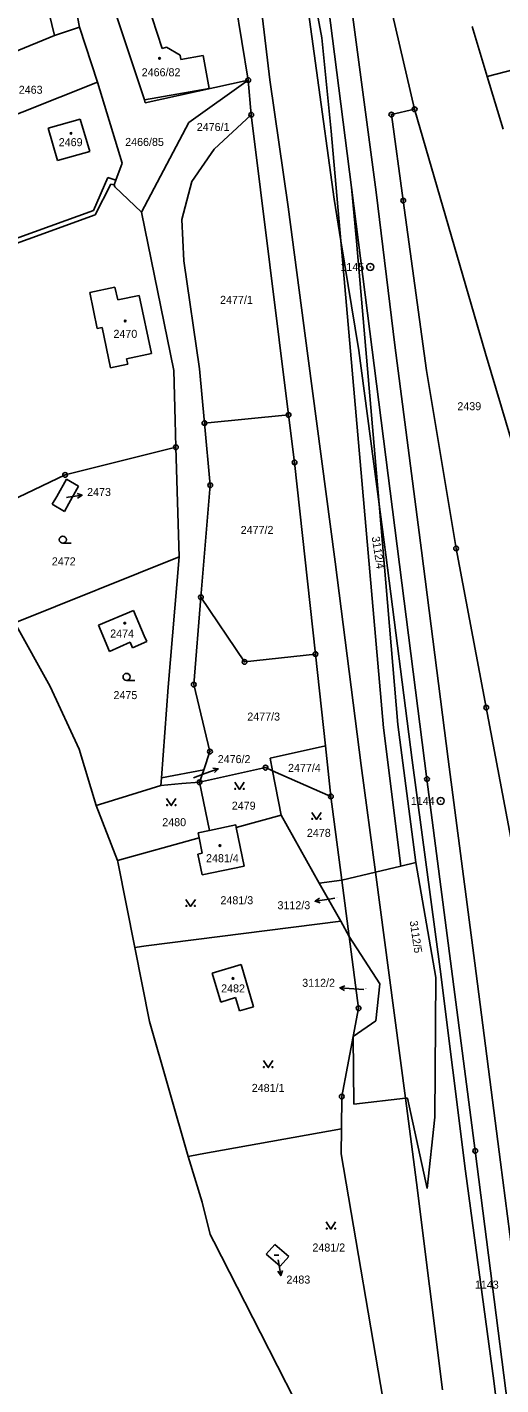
# Model space of a CAD drawing. Extents: x -736345 to -729997, y -1130177 to -1122501.
# Drawn here: x -733345 to -733244.4, y -1127962.5 to -1127674.1 of the extents above; entities that cross this region are included whole.
import ezdxf

# ---------------------------------------------------------------- set-up
doc = ezdxf.new("R2010")
doc.units = 0
for name, color, linetype in [('Vrstva 1', 7, 'Continuous'), ('Vrstva 10', 7, 'Continuous'), ('Vrstva 16', 7, 'Continuous'), ('Vrstva 17', 7, 'Continuous'), ('Vrstva 18', 7, 'Continuous'), ('Vrstva 19', 7, 'Continuous'), ('Vrstva 25', 7, 'Continuous'), ('Vrstva 4', 7, 'Continuous')]:
    doc.layers.add(name, color=color, linetype=linetype)

msp = doc.modelspace()

# ---------------------------------------------------------------- linework, layer by layer
at = {"layer": 'Vrstva 1'}
for points in [[(-733333.91, -1127674.1), (-733339.71, -1127643.99)], [(-733288.73, -1127642.56), (-733282.45, -1127676.33)], [(-733303.42, -1127652.45), (-733298.06, -1127685.32)], [(-733282.85, -1127655.34), (-733276.12, -1127708.15)], [(-733262.71, -1127691.52), (-733271.41, -1127654.27)], [(-733341.96, -1127664.36), (-733339.19, -1127675.85)], [(-733319.54, -1127668.85), (-733316.3, -1127678.59)], [(-733320.11, -1127689.5), (-733326.23, -1127671.02)], [(-733409.51, -1127704.75), (-733339.19, -1127675.85)], [(-733339.19, -1127675.85), (-733333.91, -1127674.1)], [(-733333.91, -1127674.1), (-733330.07, -1127685.76)], [(-733282.45, -1127676.33), (-733280.41, -1127696.21)], [(-733250.49, -1127673.94), (-733247.3, -1127684.57)], [(-733316.3, -1127678.59), (-733315.39, -1127678.31)], [(-733315.39, -1127678.31), (-733312.5, -1127680.04)], [(-733247.3, -1127684.57), (-733217.33, -1127676.81)], [(-733312.5, -1127680.04), (-733312.34, -1127680.96)], [(-733312.34, -1127680.96), (-733307.65, -1127680.12)], [(-733307.65, -1127680.12), (-733306.36, -1127687.1)], [(-733243.94, -1127695.79), (-733247.3, -1127684.57)], [(-733402.84, -1127714.76), (-733330.07, -1127685.76)], [(-733330.07, -1127685.76), (-733324.85, -1127703.01)], [(-733306.36, -1127687.1), (-733320.11, -1127689.5)], [(-733298.06, -1127685.32), (-733319.96, -1127690.18)], [(-733298.06, -1127685.32), (-733310.68, -1127694.33)], [(-733297.41, -1127692.7), (-733298.06, -1127685.32)], [(-733319.96, -1127690.18), (-733320.11, -1127689.5)], [(-733333.74, -1127693.66), (-733340.55, -1127695.53)], [(-733331.71, -1127700.53), (-733333.74, -1127693.66)], [(-733297.41, -1127692.7), (-733305.27, -1127699.97)], [(-733297.41, -1127692.7), (-733289.47, -1127756.46)], [(-733267.66, -1127692.67), (-733262.71, -1127691.52)], [(-733265.12, -1127710.93), (-733267.66, -1127692.67)], [(-733262.71, -1127691.52), (-733247.65, -1127743.42)], [(-733340.55, -1127695.53), (-733338.57, -1127702.44)], [(-733320.7, -1127713.36), (-733310.68, -1127694.33)], [(-733280.41, -1127696.21), (-733278.38, -1127719.49)], [(-733338.57, -1127702.44), (-733331.71, -1127700.53)], [(-733305.27, -1127699.97), (-733310.06, -1127706.87)], [(-733324.85, -1127703.01), (-733326.2, -1127706.62)], [(-733327.89, -1127705.99), (-733330.88, -1127713)], [(-733327.23, -1127707.46), (-733330.54, -1127713.94)], [(-733326.2, -1127706.62), (-733327.89, -1127705.99)], [(-733326.55, -1127707.56), (-733327.23, -1127707.46)], [(-733326.2, -1127706.62), (-733326.55, -1127707.56)], [(-733326.55, -1127707.56), (-733326.38, -1127708.04)], [(-733326.38, -1127708.04), (-733320.7, -1127713.36)], [(-733310.06, -1127706.87), (-733312.16, -1127714.93)], [(-733275.04, -1127719.57), (-733276.12, -1127708.15)], [(-733276.12, -1127708.15), (-733260.09, -1127833.79)], [(-733260.22, -1127747.01), (-733265.12, -1127710.93)], [(-733330.54, -1127713.94), (-733374.08, -1127729.71)], [(-733352.7, -1127720.9), (-733330.88, -1127713)], [(-733320.7, -1127713.36), (-733313.87, -1127747.03)], [(-733312.16, -1127714.93), (-733311.71, -1127723.73)], [(-733278.38, -1127719.49), (-733269.36, -1127822.94)], [(-733270.27, -1127775.42), (-733275.04, -1127719.57)], [(-733311.71, -1127723.73), (-733308.41, -1127746.64)], [(-733331.69, -1127730.47), (-733326.35, -1127729.32)], [(-733330.12, -1127738.08), (-733331.69, -1127730.47)], [(-733326.35, -1127729.32), (-733325.77, -1127732.01)], [(-733325.77, -1127732.01), (-733321.2, -1127731.11)], [(-733321.2, -1127731.11), (-733318.6, -1127743.41)], [(-733329.05, -1127737.86), (-733330.12, -1127738.08)], [(-733327.3, -1127746.42), (-733329.05, -1127737.86)], [(-733323.63, -1127745.64), (-733327.3, -1127746.42)], [(-733318.6, -1127743.41), (-733323.87, -1127744.51)], [(-733323.87, -1127744.51), (-733323.63, -1127745.64)], [(-733247.65, -1127743.42), (-733218.54, -1127841.28)], [(-733313.87, -1127747.03), (-733313.57, -1127757.66)], [(-733308.41, -1127746.64), (-733307.34, -1127758.18)], [(-733253.92, -1127784.81), (-733260.22, -1127747.01)], [(-733289.47, -1127756.46), (-733307.34, -1127758.18)], [(-733288.21, -1127766.53), (-733289.47, -1127756.46)], [(-733313.57, -1127757.66), (-733313.41, -1127763.31)], [(-733307.34, -1127758.18), (-733306.12, -1127771.4)], [(-733336.94, -1127769.2), (-733313.41, -1127763.31)], [(-733313.41, -1127763.31), (-733312.75, -1127786.6)], [(-733283.78, -1127807.26), (-733288.21, -1127766.53)], [(-733356.8, -1127778.66), (-733336.94, -1127769.2)], [(-733338.72, -1127773.77), (-733336.61, -1127770.12)], [(-733336.61, -1127770.12), (-733334.06, -1127771.58)], [(-733334.06, -1127771.58), (-733336.14, -1127775.25)], [(-733306.12, -1127771.4), (-733308.09, -1127795.17)], [(-733339.67, -1127775.43), (-733338.72, -1127773.77)], [(-733337.1, -1127776.94), (-733339.67, -1127775.43)], [(-733336.14, -1127775.25), (-733337.1, -1127776.94)], [(-733266.27, -1127822.2), (-733270.27, -1127775.42)], [(-733247.52, -1127818.62), (-733253.92, -1127784.81)], [(-733312.75, -1127786.6), (-733347.62, -1127800.59)], [(-733315.08, -1127814.26), (-733312.75, -1127786.6)], [(-733308.09, -1127795.17), (-733309.63, -1127813.72)], [(-733298.84, -1127808.9), (-733308.09, -1127795.17)], [(-733347.62, -1127800.59), (-733340.09, -1127814.1)], [(-733329.88, -1127801.08), (-733322.38, -1127797.96)], [(-733322.38, -1127797.96), (-733320.13, -1127803.38)], [(-733329.88, -1127801.08), (-733327.53, -1127806.72)], [(-733320.13, -1127803.38), (-733319.59, -1127804.59)], [(-733327.53, -1127806.72), (-733323.15, -1127804.71)], [(-733322.61, -1127805.92), (-733323.15, -1127804.71)], [(-733319.59, -1127804.59), (-733322.61, -1127805.92)], [(-733283.78, -1127807.26), (-733298.84, -1127808.9)], [(-733281.67, -1127826.74), (-733283.78, -1127807.26)], [(-733340.09, -1127814.1), (-733333.92, -1127827.43)], [(-733315.08, -1127814.26), (-733316.5, -1127833.54)], [(-733309.63, -1127813.72), (-733306.17, -1127827.97)], [(-733242.11, -1127847.38), (-733247.52, -1127818.62)], [(-733269.36, -1127822.94), (-733265.66, -1127852.29)], [(-733262.46, -1127851.52), (-733266.27, -1127822.2)], [(-733333.92, -1127827.43), (-733330.31, -1127839.4)], [(-733306.17, -1127827.97), (-733307.48, -1127831.82)], [(-733293.39, -1127829.38), (-733281.67, -1127826.74)], [(-733292.88, -1127832.03), (-733293.39, -1127829.38)], [(-733280.5, -1127837.48), (-733281.67, -1127826.74)], [(-733316.5, -1127833.54), (-733307.48, -1127831.82)], [(-733308.39, -1127834.48), (-733294.38, -1127831.37)], [(-733307.48, -1127831.82), (-733308.39, -1127834.48)], [(-733294.38, -1127831.37), (-733292.88, -1127832.03)], [(-733292.88, -1127832.03), (-733291.07, -1127841.49)], [(-733292.88, -1127832.03), (-733280.5, -1127837.48)], [(-733328.71, -1127838.91), (-733316.62, -1127835.16)], [(-733316.5, -1127833.54), (-733316.62, -1127835.16)], [(-733316.62, -1127835.16), (-733312.16, -1127834.74)], [(-733312.16, -1127834.74), (-733308.39, -1127834.48)], [(-733306.3, -1127844.71), (-733308.39, -1127834.48)], [(-733260.09, -1127833.79), (-733249.85, -1127912.77)], [(-733280.5, -1127837.48), (-733278.17, -1127855.3)], [(-733330.31, -1127839.4), (-733328.71, -1127838.91)], [(-733325.84, -1127851.06), (-733330.31, -1127839.4)], [(-733300.7, -1127843.53), (-733306.3, -1127844.71)], [(-733300.58, -1127844.11), (-733300.7, -1127843.53)], [(-733291.07, -1127841.49), (-733300.58, -1127844.11)], [(-733282.96, -1127855.93), (-733291.07, -1127841.49)], [(-733308.45, -1127846.27), (-733325.84, -1127851.06)], [(-733306.3, -1127844.71), (-733308.66, -1127845.21)], [(-733308.66, -1127845.21), (-733308.45, -1127846.27)], [(-733308.45, -1127846.27), (-733307.81, -1127849.5)], [(-733298.9, -1127852.29), (-733300.58, -1127844.11)], [(-733307.81, -1127849.5), (-733308.72, -1127849.71)], [(-733325.84, -1127851.06), (-733325.77, -1127851.39)], [(-733325.77, -1127851.39), (-733322.16, -1127869.55)], [(-733308.72, -1127849.71), (-733307.82, -1127854.12)], [(-733307.82, -1127854.12), (-733298.9, -1127852.29)], [(-733265.66, -1127852.29), (-733271.05, -1127853.59)], [(-733262.46, -1127851.52), (-733265.66, -1127852.29)], [(-733258.19, -1127875.91), (-733262.46, -1127851.52)], [(-733278.17, -1127855.3), (-733282.96, -1127855.93)], [(-733271.05, -1127853.59), (-733278.17, -1127855.3)], [(-733278.17, -1127855.3), (-733276.61, -1127867.23)], [(-733278.42, -1127864), (-733282.96, -1127855.93)], [(-733319.71, -1127869.24), (-733278.42, -1127864)], [(-733278.42, -1127864), (-733276.61, -1127867.23)], [(-733322.16, -1127869.55), (-733319.71, -1127869.24)], [(-733322.16, -1127869.55), (-733319.03, -1127885.28)], [(-733276.61, -1127867.23), (-733274.61, -1127882.47)], [(-733276.61, -1127867.23), (-733270.12, -1127877.27)], [(-733299.53, -1127873.18), (-733305.71, -1127875)], [(-733305.71, -1127875), (-733303.89, -1127881.17)], [(-733296.9, -1127882.16), (-733299.53, -1127873.18)], [(-733270.12, -1127877.27), (-733270.97, -1127885.15)], [(-733258.41, -1127905.64), (-733258.19, -1127875.91)], [(-733303.89, -1127881.17), (-733300.77, -1127880.22)], [(-733300.77, -1127880.22), (-733299.91, -1127883.05)], [(-733299.91, -1127883.05), (-733296.9, -1127882.16)], [(-733274.61, -1127882.47), (-733275.76, -1127888.49)], [(-733319.03, -1127885.28), (-733310.84, -1127913.93)], [(-733270.97, -1127885.15), (-733275.76, -1127888.49)], [(-733275.76, -1127888.49), (-733278.19, -1127901.22)], [(-733275.76, -1127888.49), (-733275.66, -1127902.87)], [(-733278.19, -1127901.22), (-733278.26, -1127908.05)], [(-733264.69, -1127901.6), (-733264.21, -1127901.54)], [(-733264.21, -1127901.54), (-733260.06, -1127920.77)], [(-733264.69, -1127901.6), (-733275.66, -1127902.87)], [(-733260.06, -1127920.77), (-733258.41, -1127905.64)], [(-733278.26, -1127908.05), (-733308.23, -1127913.46)], [(-733278.31, -1127913.42), (-733278.26, -1127908.05)], [(-733249.85, -1127912.77), (-733239.29, -1127995.28)], [(-733308.23, -1127913.46), (-733310.84, -1127913.93)], [(-733310.84, -1127913.93), (-733307.86, -1127923.64)], [(-733268.93, -1127968.62), (-733278.31, -1127913.42)], [(-733307.86, -1127923.64), (-733306.1, -1127930.53)], [(-733306.1, -1127930.53), (-733305.39, -1127932.01)], [(-733305.39, -1127932.01), (-733295.44, -1127951.41)], [(-733292.4, -1127932.68), (-733294.23, -1127934.71)], [(-733289.45, -1127935.19), (-733292.4, -1127932.68)], [(-733294.23, -1127934.71), (-733291.26, -1127937.28)], [(-733291.26, -1127937.28), (-733289.45, -1127935.19)], [(-733295.44, -1127951.41), (-733284.6, -1127972.65)]]:
    msp.add_lwpolyline(points, dxfattribs=at)
at = {"layer": 'Vrstva 10'}
for points in [[(-733277.96, -1127655.94), (-733270.89, -1127709.16)], [(-733270.89, -1127709.16), (-733266.89, -1127741.62)], [(-733266.89, -1127741.62), (-733261.27, -1127785.24)], [(-733261.27, -1127785.24), (-733255.6, -1127829.59)], [(-733255.6, -1127829.59), (-733249.92, -1127872.91)], [(-733249.92, -1127872.91), (-733244.49, -1127915.19)], [(-733244.49, -1127915.19), (-733238.52, -1127961.03)]]:
    msp.add_lwpolyline(points, dxfattribs=at)
at = {"layer": 'Vrstva 16'}
for points in [[(-733336.65, -1127773.96), (-733336.32, -1127773.92)], [(-733309.69, -1127833.5), (-733307.25, -1127832.63)], [(-733279.67, -1127859.08), (-733280.88, -1127859.27)], [(-733273.48, -1127878.48), (-733275.6, -1127878.33)], [(-733291.68, -1127935.89), (-733291.62, -1127936.29)]]:
    msp.add_lwpolyline(points, dxfattribs=at)
at = {"layer": 'Vrstva 25'}
for points in [[(-733336.32, -1127773.92), (-733333.348, -1127773.513)], [(-733334.407, -1127773.154), (-733333.348, -1127773.513), (-733334.271, -1127774.143)], [(-733337.42, -1127783.7), (-733335.67, -1127783.7)], [(-733323.89, -1127812.84), (-733322.14, -1127812.84)], [(-733307.25, -1127832.63), (-733304.424, -1127831.624)], [(-733305.534, -1127831.489), (-733304.424, -1127831.624), (-733305.199, -1127832.431)], [(-733300.89, -1127834.48), (-733299.89, -1127835.98), (-733298.89, -1127834.48)], [(-733315.39, -1127837.91), (-733314.39, -1127839.41), (-733313.39, -1127837.91)], [(-733284.57, -1127840.86), (-733283.57, -1127842.36), (-733282.57, -1127840.86)], [(-733311.28, -1127859.34), (-733310.28, -1127860.84), (-733309.28, -1127859.34)], [(-733282.778, -1127860.073), (-733283.843, -1127859.734), (-733282.933, -1127859.086)], [(-733280.88, -1127859.27), (-733283.843, -1127859.734)], [(-733277.63, -1127878.685), (-733278.592, -1127878.116), (-733277.559, -1127877.689)], [(-733275.6, -1127878.33), (-733278.592, -1127878.116)], [(-733294.81, -1127893.57), (-733293.81, -1127895.07), (-733292.81, -1127893.57)], [(-733281.49, -1127927.86), (-733280.49, -1127929.36), (-733279.49, -1127927.86)], [(-733292.52, -1127934.94), (-733291.52, -1127934.94)], [(-733290.807, -1127938.184), (-733291.141, -1127939.251), (-733291.793, -1127938.344)], [(-733291.62, -1127936.29), (-733291.141, -1127939.251)]]:
    msp.add_lwpolyline(points, dxfattribs=at)
for centre, radius in [((-733316.88, -1127680.72), 0.175), ((-733298.06, -1127685.32), 0.5), ((-733298.06, -1127685.32), 0.032), ((-733262.71, -1127691.52), 0.5), ((-733297.41, -1127692.7), 0.5), ((-733297.41, -1127692.7), 0.032), ((-733267.66, -1127692.67), 0.5), ((-733267.66, -1127692.67), 0.032), ((-733262.71, -1127691.52), 0.032), ((-733335.7, -1127696.65), 0.175), ((-733265.12, -1127710.93), 0.5), ((-733265.12, -1127710.93), 0.032), ((-733272.14, -1127725.02), 0.75), ((-733272.14, -1127725.02), 0.032), ((-733324.18, -1127736.51), 0.175), ((-733289.47, -1127756.46), 0.5), ((-733289.47, -1127756.46), 0.032), ((-733307.34, -1127758.18), 0.5), ((-733307.34, -1127758.18), 0.032), ((-733313.41, -1127763.31), 0.5), ((-733313.41, -1127763.31), 0.032), ((-733288.21, -1127766.53), 0.5), ((-733336.94, -1127769.2), 0.5), ((-733288.21, -1127766.53), 0.032), ((-733336.94, -1127769.2), 0.032), ((-733306.12, -1127771.4), 0.5), ((-733306.12, -1127771.4), 0.032), ((-733337.42, -1127782.95), 0.75), ((-733253.92, -1127784.81), 0.5), ((-733253.92, -1127784.81), 0.032), ((-733308.09, -1127795.17), 0.5), ((-733308.09, -1127795.17), 0.032), ((-733324.27, -1127800.68), 0.175), ((-733298.84, -1127808.9), 0.5), ((-733298.84, -1127808.9), 0.032), ((-733283.78, -1127807.26), 0.5), ((-733283.78, -1127807.26), 0.032), ((-733323.89, -1127812.09), 0.75), ((-733309.63, -1127813.72), 0.5), ((-733309.63, -1127813.72), 0.032), ((-733247.52, -1127818.62), 0.5), ((-733247.52, -1127818.62), 0.032), ((-733306.17, -1127827.97), 0.5), ((-733306.17, -1127827.97), 0.032), ((-733294.38, -1127831.37), 0.5), ((-733294.38, -1127831.37), 0.032), ((-733308.39, -1127834.48), 0.5), ((-733308.39, -1127834.48), 0.032), ((-733260.09, -1127833.79), 0.5), ((-733260.09, -1127833.79), 0.032), ((-733300.79, -1127835.88), 0.1), ((-733298.99, -1127835.88), 0.1), ((-733280.5, -1127837.48), 0.5), ((-733280.5, -1127837.48), 0.032), ((-733257.18, -1127838.44), 0.75), ((-733315.29, -1127839.31), 0.1), ((-733313.49, -1127839.31), 0.1), ((-733257.18, -1127838.44), 0.032), ((-733284.47, -1127842.26), 0.1), ((-733282.67, -1127842.26), 0.1), ((-733304.07, -1127847.92), 0.175), ((-733311.18, -1127860.74), 0.1), ((-733309.38, -1127860.74), 0.1), ((-733301.28, -1127876.14), 0.175), ((-733274.61, -1127882.47), 0.5), ((-733274.61, -1127882.47), 0.032), ((-733294.71, -1127894.97), 0.1), ((-733292.91, -1127894.97), 0.1), ((-733278.19, -1127901.22), 0.5), ((-733278.19, -1127901.22), 0.032), ((-733249.85, -1127912.77), 0.5), ((-733249.85, -1127912.77), 0.032), ((-733281.39, -1127929.26), 0.1), ((-733279.59, -1127929.26), 0.1)]:
    msp.add_circle(centre, radius, dxfattribs=at)
at = {"layer": 'Vrstva 4'}
for points in [[(-733287.33, -1127655.87), (-733279.83, -1127710.64)], [(-733296.82, -1127657.23), (-733293.46, -1127685.29)], [(-733293.46, -1127685.29), (-733289.57, -1127712.22)], [(-733279.83, -1127710.64), (-733278.38, -1127719.49)], [(-733289.57, -1127712.22), (-733285.41, -1127743.92)], [(-733278.38, -1127719.49), (-733274.56, -1127742.8)], [(-733274.56, -1127742.8), (-733270.27, -1127775.42)], [(-733285.41, -1127743.92), (-733279.61, -1127787.64)], [(-733270.27, -1127775.42), (-733268.85, -1127786.19)], [(-733268.85, -1127786.19), (-733263.26, -1127829.79)], [(-733279.61, -1127787.64), (-733274.09, -1127830.9)], [(-733274.09, -1127830.9), (-733271.05, -1127853.59)], [(-733263.26, -1127829.79), (-733257.29, -1127874.15)], [(-733271.05, -1127853.59), (-733268.11, -1127875.47)], [(-733268.11, -1127875.47), (-733264.69, -1127901.6)], [(-733257.29, -1127874.15), (-733251.92, -1127917.1)], [(-733264.69, -1127901.6), (-733262.35, -1127919.49)], [(-733251.92, -1127917.1), (-733245.9, -1127961.64)], [(-733262.35, -1127919.49), (-733256.82, -1127963.54)], [(-733239.03, -1128017.71), (-733245.9, -1127961.64)]]:
    msp.add_lwpolyline(points, dxfattribs=at)

# ---------------------------------------------------------------- texts
at = {"layer": 'Vrstva 16'}
for s, p in [('2463', (-733346.78, -1127688.24)), ('2473', (-733332.263, -1127773.67)), ('2476/2', (-733304.53, -1127830.41)), ('3112/3', (-733291.837, -1127861.44)), ('3112/2', (-733286.587, -1127877.92)), ('2483', (-733289.94, -1127940.95))]:
    msp.add_text(s, height=1.7, dxfattribs=at).set_placement(p)
at = {"layer": 'Vrstva 17'}
for s, p in [('1145', (-733278.481, -1127725.87)), ('1144', (-733263.521, -1127839.29)), ('1143', (-733249.921, -1127942.03))]:
    msp.add_text(s, height=1.7, dxfattribs=at).set_placement(p)
at = {"layer": 'Vrstva 18'}
for s, height, p in [('2476/1', 1.7, (-733308.98, -1127696.14)), ('2466/85', 1.7, (-733324.18, -1127699.32)), ('2477/1', 1.7, (-733304.03, -1127732.86)), ('2439', 1.7, (-733253.64, -1127755.45)), ('2473', 0.1, (-733336.608, -1127773.76)), ('2477/2', 1.7, (-733299.65, -1127781.73)), ('2472', 1.7, (-733339.75, -1127788.41)), ('2475', 1.7, (-733326.66, -1127816.81)), ('2477/3', 1.7, (-733298.25, -1127821.37)), ('2477/4', 1.7, (-733289.6, -1127832.27)), ('2476/2', 0.1, (-733309.49, -1127833.3)), ('2479', 1.7, (-733301.54, -1127840.29)), ('2480', 1.7, (-733316.3, -1127843.8)), ('2478', 1.7, (-733285.59, -1127846.07)), ('2481/3', 1.7, (-733303.95, -1127860.38)), ('3112/3', 0.1, (-733279.47, -1127858.88)), ('3112/2', 0.1, (-733273.28, -1127878.28)), ('2481/1', 1.7, (-733297.3, -1127900.24)), ('2481/2', 1.7, (-733284.42, -1127934.14))]:
    msp.add_text(s, height=height, dxfattribs=at).set_placement(p)
for s, rotation, p in [('3112/4', 278.90222, (-733271.842, -1127782.396)), ('3112/5', 278.40221, (-733263.773, -1127863.978))]:
    msp.add_text(s, height=1.7, rotation=rotation, dxfattribs=at).set_placement(p)
at = {"layer": 'Vrstva 19'}
for s, height, p in [('2466/82', 1.7, (-733320.67, -1127684.52)), ('2469', 1.7, (-733338.29, -1127699.37)), ('2470', 1.7, (-733326.67, -1127740.08)), ('2474', 1.7, (-733327.36, -1127803.73)), ('2481/4', 1.7, (-733307.01, -1127851.45)), ('2482', 1.7, (-733303.8, -1127879.11)), ('2483', 0.1, (-733291.48, -1127935.69))]:
    msp.add_text(s, height=height, dxfattribs=at).set_placement(p)

doc.saveas('drawing.dxf')
